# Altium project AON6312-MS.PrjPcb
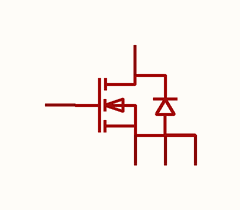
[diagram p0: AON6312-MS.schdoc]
1 sheet, 1 parts. Net scope: global (net labels, ports and power ports of the same name join across sheets).

## Sheet AON6312-MS.schdoc
size 127 x 101 mm

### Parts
Q?  aon6312-ms  [TDSON-8_L5.9-W5.2-P1.27-BL]  (value not drawn)

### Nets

Not connected (* = marked no-connect by the designer): Q? 1(S) 2(S) 3(S) 4(G) 5(D)

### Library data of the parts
Q? = aon6312-ms: 数量:1个N沟道;漏源电压(Vdss):30V;连续漏极电流(Id):150A;导通电阻(RDS(on)):3.2mΩ@4.5V;耗散功率(Pd):187W;阈值电压(Vgs(th)):2.5V;; Manufacturer: MSKSEMI(美森科); AddInBom: yes; ModelId: ff3d8edf19694f3eb1c5df98919f3bc8; ModelTransform: 216.9287,242.5192,0,0,0,0,0,43.307,0; Number: 1个N沟道; Drain to Source Voltage: 30V; Current - Continuous Drain(Id): 150A; Pd - Power Dissipation: 187W; Gate Threshold Voltage (Vgs(th)): 2.5V; Gate Charge(Qg): 56.9nC@10V; Input Capacitance(Ciss): 4.345nF; Reverse Transfer Capacitance (Crss@Vds): 225pF; Type: N沟道; Output Capacitance(Coss): 340pF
